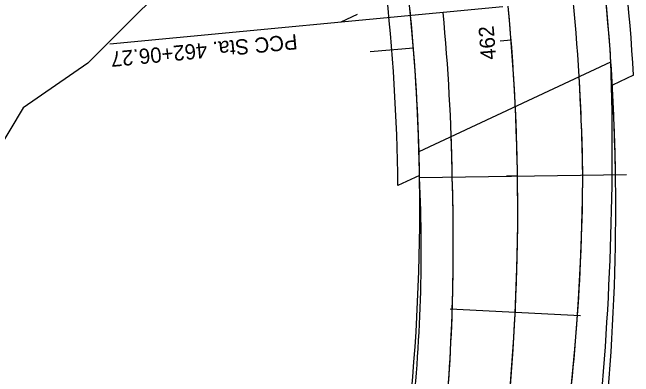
# Model space of a CAD drawing. Extents: x 2355002 to 2355569, y 708374 to 709566.
# Drawn here: x 2355270.5 to 2355384.6, y 709184.4 to 709251.3 of the extents above; entities that cross this region are included whole.
import ezdxf

# ---------------------------------------------------------------- set-up
doc = ezdxf.new("R2010")
doc.units = 0
for name, color, linetype in [('BD_X_Building', 7, 'Continuous'), ('BR_X_Gen_Approach_Slab', 7, 'Continuous'), ('DR_X_Underdrain', 7, 'Continuous'), ('DT_X_Slope_Break_Line', 7, 'Continuous'), ('HY_X_Water_Edge', 7, 'Continuous'), ('PM_X_CL_Double_Solid', 7, 'Continuous'), ('PM_X_Edge_Line', 7, 'Continuous'), ('PV_X_EOP', 7, 'Continuous'), ('RD_X_GR_Lt', 7, 'Continuous'), ('RD_X_GR_Rt', 7, 'Continuous'), ('RD_X_Wall', 7, 'Continuous'), ('SH_Text', 7, 'Continuous'), ('UT_X_Water_Cells', 7, 'Continuous'), ('VG_X_Tree_Line_Rt', 7, 'Continuous')]:
    doc.layers.add(name, color=color, linetype=linetype)

msp = doc.modelspace()

# ---------------------------------------------------------------- linework, layer by layer
at = {"layer": 'BD_X_Building'}
for p, q in [((2355345.33, 709220.96), (2355383.33, 709221.53)), ((2355350.92, 709196.82), (2355374.89, 709195.65))]:
    msp.add_line(p, q, dxfattribs=at)
at = {"layer": 'BR_X_Gen_Approach_Slab'}
msp.add_line((2355345.23, 709225.72), (2355380.49, 709242.22), dxfattribs=at)
for radius, start in [(408.32, 3.7814), (372.32, 1.6047)]:
    msp.add_arc((2354973.05, 709215.29), radius, start, 5.4603, dxfattribs=at)
at = {"layer": 'DR_X_Underdrain'}
msp.add_line((2355336.23, 709244.14), (2355344.21, 709244.77), dxfattribs=at)
at = {"layer": 'DT_X_Slope_Break_Line'}
msp.add_line((2355330.92, 709249.59), (2355333.9, 709250.99), dxfattribs=at)
at = {"layer": 'HY_X_Water_Edge'}
msp.add_lwpolyline([(2355337.75, 709284.56), (2355335.6, 709283.02), (2355327.11, 709277.25), (2355320.96, 709270.85), (2355308.96, 709263.9), (2355298.46, 709255.86), (2355294.04, 709251.65), (2355284.37, 709241.95), (2355272.47, 709233.76), (2355267.36, 709225.23), (2355264.27, 709216.73)], dxfattribs=at)
at = {"layer": 'PM_X_CL_Double_Solid'}
for start in [334.3, 353.532]:
    msp.add_arc((2354973.05, 709215.29), 390.32, start, 5.4609, dxfattribs=at)
at = {"layer": 'PM_X_Edge_Line'}
for centre, radius, start, end in [((2354973.05, 709215.3), 402.32, 0.8706, 5.4593), ((2354973.05, 709215.3), 378.32, 0.8705, 5.4593), ((2354972.82, 709208.78), 378.71, 345.5839, 1.8559), ((2354973.64, 709223.69), 401.69, 338.83, 359.6749)]:
    msp.add_arc(centre, radius, start, end, dxfattribs=at)
at = {"layer": 'PV_X_EOP'}
for centre, radius, start, end in [((2354857.73, 709226.22), 523, 353.7662, 1.7538), ((2354973.05, 709215.3), 402.32, 0.8706, 3.4469), ((2354973.05, 709215.3), 378.32, 0.8705, 1.9978), ((2355066.64, 709207.56), 279.01, 352.9182, 2.7522), ((2354972.82, 709208.78), 378.71, 354.5146, 1.8559), ((2354973.64, 709223.69), 401.69, 352.3321, 359.6749)]:
    msp.add_arc(centre, radius, start, end, dxfattribs=at)
at = {"layer": 'RD_X_GR_Lt'}
msp.add_arc((2354973.05, 709215.29), 408.32, 354.6047, 5.4609, dxfattribs=at)
at = {"layer": 'RD_X_GR_Rt'}
for centre, radius, start, end in [((2355104.75, 709227.89), 240.02, 5.4603, 6.3021), ((2354973.05, 709215.29), 372.32, 338.2199, 5.4609)]:
    msp.add_arc(centre, radius, start, end, dxfattribs=at)
at = {"layer": 'RD_X_Wall'}
for p, q in [((2355362.15, 709246.2), (2355360.16, 709246.04)), ((2355363.33, 709221.23), (2355361.33, 709221.2))]:
    msp.add_line(p, q, dxfattribs=at)
msp.add_arc((2354973.05, 709215.29), 390.32, 334.3, 5.4609, dxfattribs=at)
at = {"layer": 'SH_Text'}
msp.add_line((2355360.61, 709252.34), (2355288.41, 709245.44), dxfattribs=at)
at = {"layer": 'UT_X_Water_Cells'}
for centre, radius, start, end in [((2355104.75, 709227.89), 240.02, 5.4603, 6.6935), ((2354973.05, 709215.29), 408.32, 0.8715, 3.7814), ((2354973.05, 709215.3), 372.32, 0.8705, 1.6038)]:
    msp.add_arc(centre, radius, start, end, dxfattribs=at)
at = {"layer": 'VG_X_Tree_Line_Rt'}
for p, q in [((2355384.65, 709239.75), (2355380.75, 709237.93)), ((2355345.33, 709221.35), (2355341.35, 709219.49))]:
    msp.add_line(p, q, dxfattribs=at)
for radius, start, end in [(412.32, 3.401, 8.5044), (368.32, 0.6526, 6.4556)]:
    msp.add_arc((2354973.05, 709215.29), radius, start, end, dxfattribs=at)

# ---------------------------------------------------------------- texts
at = {"layer": 'RD_X_Wall'}
msp.add_text('462', height=2.8, rotation=94.5413, dxfattribs=at).set_placement((2355359.42, 709242.69))
at = {"layer": 'SH_Text'}
msp.add_text('PCC Sta. 462+06.27', height=2.8, rotation=185.4603, dxfattribs=at).set_placement((2355322.75, 709247.34))

doc.saveas('drawing.dxf')
